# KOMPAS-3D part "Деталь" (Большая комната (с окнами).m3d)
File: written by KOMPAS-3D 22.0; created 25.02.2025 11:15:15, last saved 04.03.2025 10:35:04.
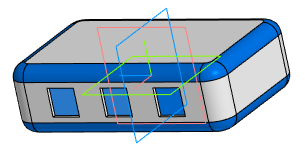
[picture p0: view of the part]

Document properties: Автор: Пользователь Windows; Полное имя файла: C:\Users\Student\Documents\Картошечка\База Сабнатика\Большая комната\Большая комната (с окнами).m3d

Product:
- Part/product: Деталь
    Масса: 2.206526

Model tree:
1. Эскиз:1
2. Элемент выдавливания:1
     Расстояние 1 = 35
3. Скругление:2  (with: Элемент выдавливания:1)
     Радиус = 10
4. Скругление:1  (with: Элемент выдавливания:1)
     Радиус = 7
5. Эскиз:2  (with: Элемент выдавливания:1, Скругление:1)
6. Элемент выдавливания:2
     Расстояние 2 = 2
7. Зеркальный массив:1
8. Экземпляр ( 1 )
9. Экземпляр ( 2 )  (with: Элемент выдавливания:2)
